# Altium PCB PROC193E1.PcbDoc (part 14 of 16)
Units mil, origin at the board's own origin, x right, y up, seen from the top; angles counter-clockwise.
Board outline 7700 x 2300 mil, 6 copper layers (Top Layer, GND 1, SIG 1, PWR, GND 2, Bottom Layer), stack 60.98 mil thick; 946 components, 667 nets, 9401 pads, 1730 vias.
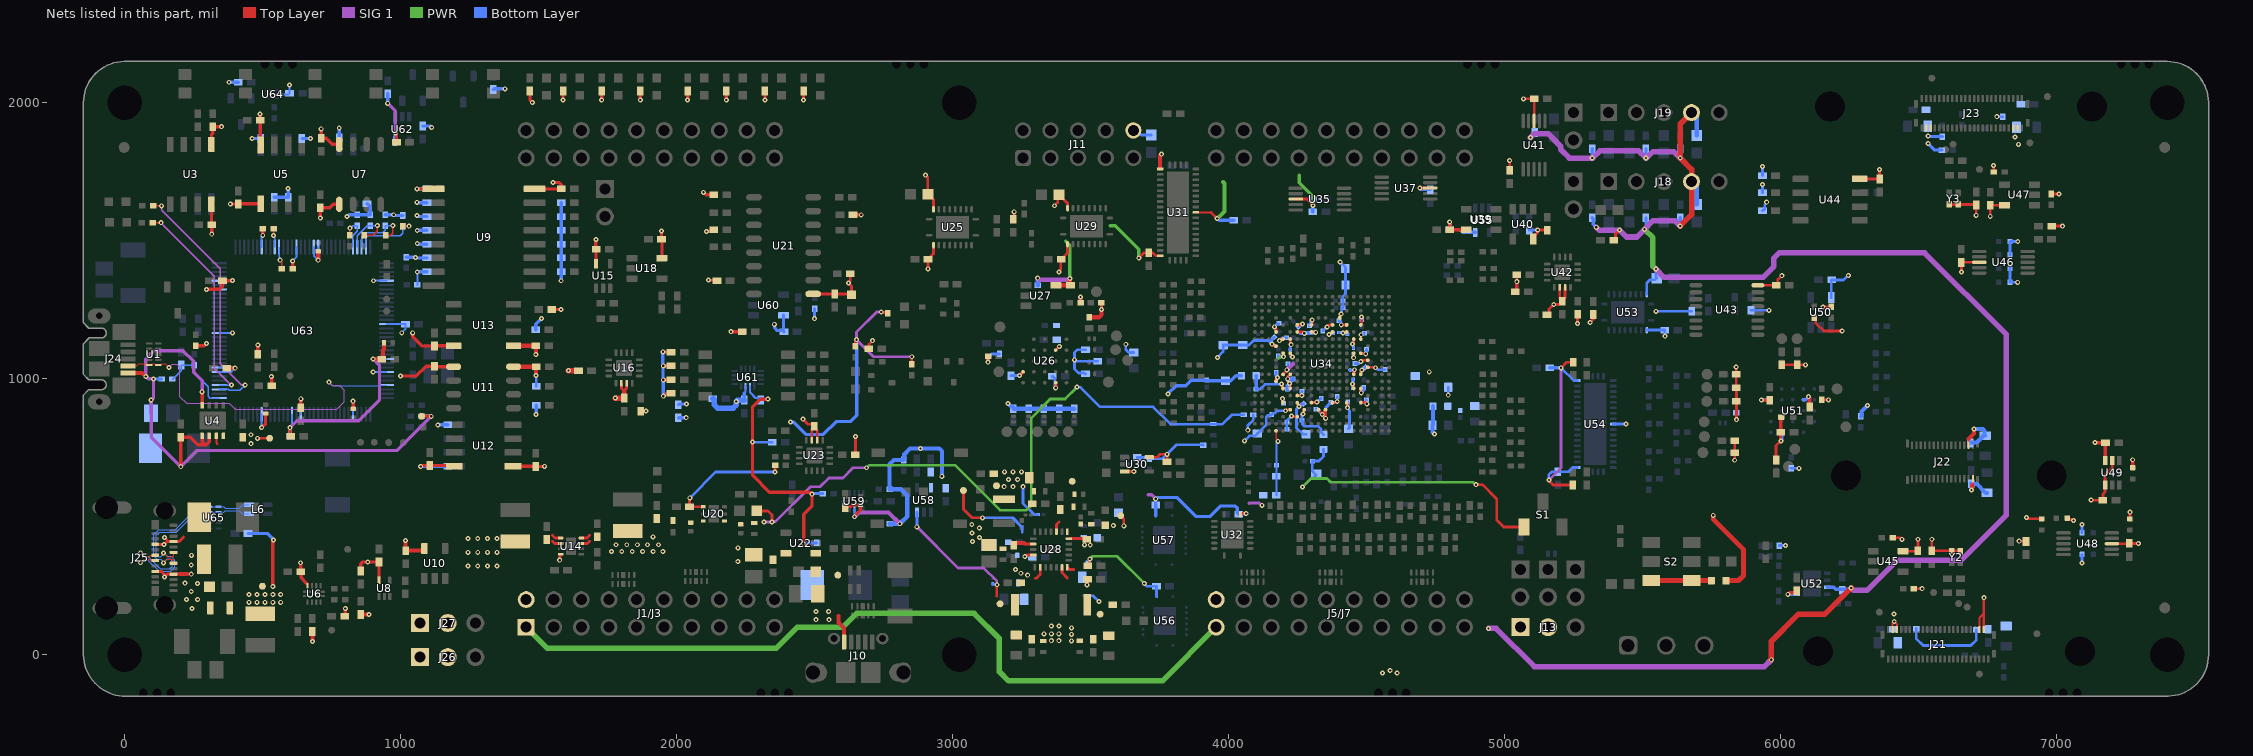
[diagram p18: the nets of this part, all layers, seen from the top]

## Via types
v1: diameter 18, hole 8, Top Layer to Bottom Layer, tented both sides, 1710 vias
v2: diameter 18, hole 8, Top Layer to Bottom Layer, tented top, 12 vias
v3: diameter 23.62, hole 11.81, Top Layer to Bottom Layer, tented both sides, 8 vias

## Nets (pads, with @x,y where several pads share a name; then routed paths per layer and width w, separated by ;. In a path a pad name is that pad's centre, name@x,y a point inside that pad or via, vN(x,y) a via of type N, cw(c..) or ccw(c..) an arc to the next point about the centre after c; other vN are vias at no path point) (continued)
USBTYPEC_DM: J25.A7 J25.B7 L6.1 U65.5 U65.6 | length 833.7
  Top Layer w4.2: v1(57.05,369.66) 70.96,355.74 88.56,355.74 93.92,361.1 J25.B7@109.7,361.1 ; v1(140.74,333.26) 154.14,346.66 173.18,346.66 176.63,343.21 J25.A7@176.63,331.57
  Bottom Layer w4.2: v1(57.05,369.66) 70.44,356.27 83.43,356.27 128.66,311.04 162.68,311.04 171.93,320.3 171.93,339.34 164.1,347.17 154.66,347.17 v1@142.12,334.63 ; v1(140.74,333.26) 140.74,336.01 130.09,346.66 117,346.66 105.46,358.19 105.46,436.7 122.26,453.5 182.76,453.5 260.66,531.4 279.6,531.4 284.84,536.64 U65.5@306.02,536.64 U65.6@338.89,536.64 358.09,536.64 363.34,531.4 414.75,531.4 426.47,543.12 L6.1@449.6,543.12
USBTYPEC_DP: J25.A6 J25.B6 L6.4 U65.4 U65.7 | length 834.3
  Top Layer w4.2: v1(57.05,333.66) 69.93,346.54 88.56,346.54 93.69,341.41 J25.B6@109.7,341.41 ; v1(140.74,369.26) 154.14,355.86 173.18,355.86 176.63,359.3 J25.A6@176.63,370.94
  Bottom Layer w4.2: v1(57.05,333.66) 70.46,347.07 79.62,347.07 124.85,301.84 166.49,301.84 181.13,316.49 181.13,343.15 167.91,356.37 153.62,356.37 142.12,367.88 v1(140.74,369.26) 140.74,366.5 130.09,355.86 120.81,355.86 114.66,362 114.66,432.89 126.07,444.3 186.57,444.3 264.47,522.2 279.6,522.2 284.84,516.95 U65.4@306.02,516.95 U65.7@338.89,516.95 358.09,516.95 363.34,522.2 414.52,522.2 425.09,511.62 L6.4@449.6,511.62
VBUS_MICRO_AB_5V0: C50.1 C51.1 D18.2 J10.1 TP14.1 U22.1 | length 103.2
  Top Layer w12: J10.1@2606.09,46.17 J10.1@2606.19,46.17
  Top Layer w15: 2586.26,141.04 2586.26,116.73 2606.09,96.89 2606.09,72.97 2606.19,72.88 J10.1@2606.19,46.17
  other v1: 2503.91,127.19 2550.94,127.19 2503.91,156.78 2550.3,156.78
VBUS_TYPEC_5V0: C4.1 C5.1 D2.2 J25.A4 J25.A9 J25.B4 J25.B9 L1.1 | length 264.9
  Top Layer w11: J25.B9@109.7,400.47 110.11,400.06 v1(142.29,400.06) 152.53,410.31 196.77,410.31 212.61,426.15 ; v1(143.88,424.98) 155.05,413.81
  Top Layer w11.5: J25.B4@109.7,302.04 132.38,302.04 144,290.42 v1(144,282.09) 154.11,292.2 J25.A9@176.63,292.2 ; J25.A9@176.68,292.25 199.48,292.25
  Top Layer w15: 199.48,292.25 227.68,292.25
  other v1: 243.58,167.7 223.39,199.95 264.16,200.22 240.71,229.19 218.04,259.4 263.8,258.72 240.71,292.2 240.71,325.66 241.5,360.53
VBUS_XDS_5V0: C2.1 C270.1 D19.2 J24.1 R390.2 R415.2 TP12.1 U4.1 U4.2 U4.8 | length 2324.1
  Top Layer w12: v1(202.72,681.67) 202.83,681.78 C2.1@202.83,788.65 237.34,788.65 264.64,761.34 295.51,761.34 ; v1(280.11,952.74) 280.11,903.63 U4.8@280.3,903.44 ; U4.1@280.3,793.2 280.3,772.1 291.07,761.34 295.51,761.34 ; U4.2@305.89,793.2 305.89,771.73 295.51,761.34 ; TP12.1@1075.19,864.22 v1(1110.3,864.22)
  Top Layer w15: J24.1@11.81,1021.01 62.95,1021.01 v1(76.14,1007.82)
  SIG 1 w12: v1(280.11,952.74) 280.11,993.51 249.65,1023.97 249.65,1063.11 210.76,1102 106.61,1102 76.14,1071.53 v1(76.14,1007.82) 77.76,1007.82 85.16,1000.42 103.06,1000.42 v1(104.21,999.27) 104.21,997.65 104.21,931.57 v1(95.75,923.11) 95.75,788.65 v1(202.72,681.67) 261.05,740 986.08,740 v1(1110.3,864.22)
  Bottom Layer w12: C270.1@95,874.79 95,922.36 v1(95.75,923.11) ; v1(104.21,999.27) 104.28,999.2 R415.2@133.15,999.2 ; R390.2@1075.19,864.22 v1(1110.3,864.22)
VCORE_1V2: C64.1 C68.1 C71.1 C179.1 C181.2 C182.2 C183.2 C184.2 C185.2 C187.2 C188.2 C189.2 C190.1 C191.1 C194.2 C196.2 C208.2 C209.1 C212.2 C214.1 C216.1 C217.2 C219.1 C220.1 C222.1 C229.2 C232.2 C235.2 C240.2 L4.2 R349.2 TP19.1 U34.D13 U34.F7 U34.F9 U34.F12 U34.F14 U34.G6 U34.G15 U34.H4 U34.J6 U34.J15 U34.K17 U34.M6 U34.M15 U34.P6 U34.P15 U34.R7 U34.V7 U58.3 | length 1794.3
  Top Layer w10: 3159.52,212.29 3159.52,252.99 v1(3160.37,253.84) ; v1(4156.85,1125.25) 4163.63,1118.47 U34.H4@4171.26,1118.47 ; U34.P6@4222.44,964.93 4222.44,978.49 4220.12,980.8 v1(4220.12,982.97) v1(4213.64,999.83) 4213.64,1007.31 U34.M6@4222.44,1016.11 ; U34.J6@4222.44,1092.88 4223.66,1091.66 4223.66,1086.4 v1(4230.92,1079.13) ; U34.G6@4222.44,1144.06 4222.44,1127.27 v1(4226.03,1123.68) ; v1(4226.67,865.67) 4229.77,862.57 U34.V7@4248.03,862.57 ; U34.R7@4248.03,939.34 v1@4264.31,939.34 ; U34.F7@4248.03,1169.65 4268.92,1169.65 v1(4273.62,1164.95) ; U34.F9@4299.21,1169.65 4299.76,1169.11 4314.34,1169.11 v1(4314.89,1168.56) ; v1(4362.66,1160.97) 4364.19,1162.5 4367.81,1162.5 4374.96,1169.65 U34.F12@4375.98,1169.65 ; U34.D13@4401.57,1220.83 4402.29,1221.56 4402.29,1227.29 4407.15,1232.15 v1(4407.15,1234.31) ; v1(4413.59,1165.65) 4417.59,1169.65 U34.F14@4427.16,1169.65 ; v1(4448.4,1126.08) 4452.75,1130.43 U34.G15@4452.75,1144.06 ; v1(4448.71,980.87) 4452.75,976.83 U34.P15@4452.75,964.93 ; v1(4452.58,1076.43) 4452.75,1076.59 U34.J15@4452.75,1092.88 ; v1(4478.28,1063.05) 4482.52,1067.29 U34.K17@4503.93,1067.29
  Top Layer w12: U34.M15@4452.75,1016.11 4452.75,1029.57 v1(4455.96,1032.77)
  SIG 1 w10: v1(2869.72,463.8) 3019.15,314.38 3111.95,314.38 3159.46,266.87 3159.46,254.75 v1(3160.37,253.84)
  Bottom Layer w10: v1(2869.72,463.8) 2870.04,464.12 U58.3@2870.04,516.32 ; R349.2@3144.53,257.22 3144.53,255.54 3144.7,255.37 3158.84,255.37 v1(3160.37,253.84) ; v1(3626.9,1125.13) 3626.9,1105.14 3637.19,1094.85 C240.2@3655.94,1094.85 ; v1(3958.96,1077.54) 3979.67,1098.25 3979.67,1121.88 C235.2@3979.56,1121.99 3979.84,1122.27 C232.2@4050.77,1122.27 4073.36,1122.27 4090.3,1139.22 C229.2@4106.03,1139.22 4142.88,1139.22 v1@4155.46,1126.63 ; v1(4156.85,1125.25) v1@4155.46,1126.63 ; C222.1@4164,1150.7 4155.46,1142.16 v1@4155.46,1126.63 ; C219.1@4210.38,816.74 C220.1@4210.38,842.29 4210.38,849.38 v1(4226.67,865.67) ; 4213.35,976.19 v1(4220.12,982.97) 4233.88,996.73 C216.1@4233.88,999.6 C216.1@4233.77,999.71 ; v1(4213.64,999.83) v1@4213.75,999.71 ; v1(4226.03,1123.68) 4226.03,1121.51 4222.26,1117.74 C217.2@4222.26,1105.54 4222.26,1082.41 4225.53,1079.13 v1(4230.92,1079.13) ; v1(4264.48,939.17) 4264.68,939.37 4264.68,954.2 C209.1@4264.88,954.4 ; v1(4273.62,1164.95) v1@4274.99,1166.33 ; v1(4362.66,1160.97) 4364.82,1160.97 4368.39,1164.54 4376.76,1164.54 C196.2@4377.67,1165.44 ; C194.2@4398.05,1167.57 4411.67,1167.57 v1(4413.59,1165.65) 4425.12,1165.65 C187.2@4429.67,1161.1 ; v1(4403.62,1423.67) 4422.27,1405.02 C189.2@4422.27,1399.48 ; v1(4407.15,1234.31) 4407.15,1236.48 4409.51,1238.84 4409.51,1253.37 4412.78,1256.63 C190.1@4413.56,1256.63 4413.56,1281.74 C191.1@4413.11,1282.19 4413.11,1298.35 4423.24,1308.48 C188.2@4423.24,1339.92 C189.2@4423.24,1400.28 ; C185.2@4439.34,1031.99 4455.17,1031.99 v1(4455.96,1032.77) ; v1(4448.4,1126.08) 4448.4,1123.91 4450.67,1121.64 4450.67,1112.58 C181.2@4451.57,1111.67 ; C184.2@4449.3,965.79 4449,966.08 4449,980.58 v1(4448.71,980.87) 4450.11,982.28 4450.11,997.54 C182.2@4451.02,998.45 ; C183.2@4450.56,1090.76 4451.47,1089.85 4451.47,1077.54 v1(4452.58,1076.43) ; C179.1@4456.87,1055.34 4470.58,1055.34 v1(4478.28,1063.05)
  Bottom Layer w15: C214.1@4213.35,961.7 4213.35,976.19 ; v1(4213.64,999.83) 4213.64,996.63 4220.12,990.14 v1(4220.12,982.97) ; v1@4213.75,999.71 C216.1@4233.77,999.71 ; C212.2@4260.51,1166.13 4272.44,1166.13 v1(4273.62,1164.95) ; v1@4274.99,1166.33 C208.2@4300.57,1166.33 4301.48,1167.23 4313.56,1167.23 v1(4314.89,1168.56)
  other v1: 3357,51 3384,51 3330,76 3357,76 3384,76 3357,104 3385,104
VDD_1P8: C73.1 C75.1 C76.1 TP25.1 U28.3 | length 38.4
  Top Layer w10: U28.3@3375.64,446.5 3375.64,471.37 3385.19,480.93
VDD_XDS3V3: C3.2 C6.2 C7.2 C9.1 C10.2 C13.1 C14.1 C17.2 C18.1 C19.1 C21.1 C28.1 C29.2 C30.2 C259.1 C261.1 R5.2 R7.2 R9.2 R12.2 R379.2 R382.2 R383.1 R384.1 R385.1 R386.1 R387.1 R388.1 R392.2 R393.2 R394.2 R396.2 R397.1 R398.2 R399.2 R404.2 R406.2 TP2.1 U3.8 U4.3 U4.4 U5.1 U7.1 U9.1 U11.1 U12.8 U13.8 U63.7 U63.8 U63.16 U63.26 U63.28 U63.39 U63.47 U63.51 U63.52 U63.69 U63.79 U63.90 U63.101 U63.113 U63.122 | length 3002.7
  Top Layer w7: U4.3@331.48,793.2 331.48,767.72 335.59,763.62
  Top Layer w8: v1(480.73,784.53) TP2.1@524.75,784.53
  Top Layer w12: R5.2@257.13,1120.19 287.58,1120.19 294.88,1127.49 v1(296.51,1127.49) ; v1(296.51,1323.98) 342.35,1323.98 354.12,1335.75 C6.2@354.12,1355.66 v1(390,1355.66) ; U3.8@314.01,1632.55 314.01,1559.47 C3.2@314.83,1558.65 314.83,1524.17 v1(315,1524) ; C7.2@368.94,1038.47 v1(400,1038.47) ; v1(382.15,1633.29) C9.1@411.06,1633.29 412.28,1634.52 U5.1@491.82,1634.52 ; R7.2@481.97,1088.85 v1(481.97,1122.33) ; v1(496.08,823.57) 510,837.49 C14.1@510,874.4 ; v1(499.83,1519.85) 500,1520.01 R9.2@500,1543.19 ; v1(530.73,1008.1) 530.73,1006.48 532.27,1004.94 C13.1@532.27,974.76 ; R12.2@608.84,1399.46 v1@608.84,1426.48 ; C17.2@637.63,894.84 v1(637.63,927.56) ; v1(708.51,1582.82) C19.1@708.51,1619.96 743.12,1619.96 755.48,1632.31 U7.1@777.09,1632.31 ; v1(826.42,918.87) 827.49,917.8 C21.1@827.49,891.07 ; v1(999.09,1010.35) 1056.59,1010.35 1091.78,1045.54 C29.2@1122.11,1045.54 1124.06,1043.59 U11.1@1191.5,1043.59 ; v1(1043.03,1166.68) 1043.03,1152.11 1076.27,1118.86 C30.2@1122.11,1118.86 1122.97,1119.73 U13.8@1191.73,1119.73 ; v1(1058.6,1688.24) 1058.9,1687.95 U9.1@1118.64,1687.95 ; v1(1072,682.5) 1073.62,682.5 1076.9,685.78 1190.95,685.78 U12.8@1193.7,683.03
  Top Layer w15: v1(700.81,1429.87) C18.1@700.81,1457.63
  Bottom Layer w7: v1(296.51,1323.98) U63.26@342.35,1323.98 ; U63.7@342.35,1024.76 386.3,1024.76 v1(400,1038.47) 397.96,1040.51 U63.8@342.35,1040.51 ; U63.16@342.35,1166.5 v1@389.81,1166.5 ; U63.28@342.35,1355.47 v1@389.81,1355.47 ; v1@495.89,823.76 U63.122@495.89,871.22 ; U63.39@495.89,1477.52 495.89,1515.91 v1(499.83,1519.85) ; v1(608.19,1427.13) 621.88,1440.82 U63.47@621.88,1477.52 ; U63.113@637.63,871.22 v1@637.63,918.68 ; U63.51@684.87,1477.52 684.87,1445.81 700.62,1430.06 U63.52@700.62,1477.52 ; U63.101@826.6,871.22 v1@826.6,918.68 ; v1@900,1024.76 U63.90@948.65,1024.76 ; v1@901.19,1355.47 U63.69@948.65,1355.47 ; U63.79@948.65,1197.99 C261.1@1016.88,1197.99 1016.88,1180.12 v1(1003.44,1166.68) ; v1(1059.56,1387.43) 1060.19,1386.81 R392.2@1060.19,1340.39
  Bottom Layer w8: v1@389.81,1166.5 v1(390,1166.68) ; v1@389.81,1355.47 v1(390,1355.66) ; v1@495.89,823.76 v1(496.08,823.57) ; v1@637.63,918.68 v1(637.63,927.56) ; v1(826.42,918.87) v1@826.6,918.68 ; v1(899.81,1024.58) v1@900,1024.76 ; v1(901,1355.28) v1@901.19,1355.47
  Bottom Layer w12: R406.2@541.82,1658.14 R404.2@591.82,1658.14 591.75,1658.2 591.75,1688.94 v1(591.69,1689.01) ; v1(804.99,1587.77) 806.62,1587.77 813.22,1594.37 R398.2@889.13,1594.37 889.13,1623.21 R397.1@877.57,1634.77 ; R396.2@943.35,1594.37 v1(974.31,1594.37) 977,1591.68 R394.2@1007.56,1591.68 ; R393.2@1020,1440.93 1051.47,1440.93 v1(1052.8,1439.6) 1054.46,1437.95 R384.1@1095.02,1437.95 ; v1(1058.6,1591.68) 1062.34,1587.95 R387.1@1095.02,1587.95 ; v1(1058.6,1639.54) 1060.19,1637.95 R388.1@1095.02,1637.95 ; v1(1058.6,1688.24) 1058.9,1687.95 C259.1@1095.02,1687.95 ; v1(1059.56,1387.43) 1060.08,1387.95 R383.1@1095.02,1387.95 ; v1(1059.56,1490.13) 1061.75,1487.95 R385.1@1095.02,1487.95 ; v1(1059.56,1536.84) 1060.67,1537.95 R386.1@1095.02,1537.95 ; v1@1072.52,683.03 R379.2@1170.08,683.03 ; v1@1134.28,833.03 R382.2@1170.08,833.03
  other v1: 457.48,764.8 457.27,797.27 1134.25,833.06
VDDA18_AM261_OSC_PLL: C210.1 FB3.2 U34.U8 | length 155.3
  Top Layer w10: v1(4269.04,872.85) U34.U8@4273.62,888.16
  Bottom Layer w10: v1(4269.04,872.85) 4264.31,868.13 C210.1@4264.31,849.86 4267.33,846.85 4267.33,834.34 4273.19,828.48 4323.26,828.48 4335.36,816.38 4335.36,805.41 4343.16,797.62 FB3.2@4343.27,797.62
VDDA_AM261_1V8_LDO: C197.1 C202.1 C204.1 C205.1 C218.1 FB3.1 R320.2 S1.1 U34.T5 U34.U10 U34.U11 | length 1409.1
  Top Layer w10: v1(4195,928) 4196.12,926.88 4196.12,914.47 U34.T5@4196.85,913.75 ; U34.U10@4324.8,888.16 4324.8,887.13 v1@4337,874.93 ; v1(4351.18,856.94) v1@4350.39,857.78 ; v1(4895.19,616.35) 4919.51,616.35 4970.75,565.12 4970.75,488.24 4996.06,462.93 S1.1@5069.76,462.93 ; v1@4350.39,857.78 U34.U11@4350.39,888.16 v1(4338.53,870.34) v1@4350.39,857.78
  PWR w10: v1(4266.94,607.69) 4298.25,639 4355.69,639 4369.34,625.35 4885.33,625.35 4894.33,616.35 v1(4895.19,616.35)
  Bottom Layer w10: v1(4068.8,813.88) 4068.8,830.35 4089.02,850.57 R320.2@4089.02,869.83 ; v1(4195,928) 4196.53,926.47 4196.53,913.39 C218.1@4196.85,913.07 ; v1(4266.94,607.69) 4297.71,638.46 4303.29,638.46 C202.1@4316.99,652.16 ; C202.1@4316.15,652.16 4302.45,665.86 C205.1@4302.45,701.73 4325.9,701.73 4343.27,719.1 FB3.1@4343.27,744.47 ; C204.1@4316.46,890.38 4317.25,890.38 4322.92,884.71 4323.9,884.71 4338.27,870.34 v1(4338.53,870.34) ; v1(4351.18,856.94) 4351.18,895.05 4369.18,913.04 C197.1@4369.18,913.83
VDDA_AM261_3V3: C161.2 C193.1 C201.1 FB2.2 U34.T9 U34.T12 | length 182.3
  Top Layer w10: U34.T9@4299.21,913.75 4316.56,913.75 v1(4318.94,916.13) ; U34.T12@4375.98,913.75 4388.45,913.75 v1(4392.89,918.18)
  Bottom Layer w10: v1(4318.94,916.13) 4331.8,928.99 C201.1@4335.28,928.99 ; C193.1@4392.64,934.88 4392.64,918.43 v1(4392.89,918.18)
  Bottom Layer w15: FB2.2@4740.2,900.65 4740.2,833.29 C161.2@4738.43,831.52 4738.43,805.98 v1(4744.79,799.61)
VDDA_AM261_3V3_USB: C230.1 FB4.2 U34.P5 | length 165.7
  Top Layer w12: v1(4190.91,980.87) U34.P5@4196.85,964.93
  Bottom Layer w10: C230.1@4098.94,962.34 4113.43,962.34 4131.11,980.02 v1@4190.06,980.02
  Bottom Layer w12: C230.1@4098.94,962.34 4099.36,962.76 FB4.2@4099.36,1011.24 ; v1@4190.06,980.02 v1(4190.91,980.87)
VDDC_XDS_1V0: C16.2 C23.2 C25.1 C265.2 U63.87 U63.115 | length 782.3
  Top Layer w12: v1(598.48,823) 598.48,794.73 C16.2@601.36,791.85
  Top Layer w15: v1(899.81,1071.82) 899.97,1071.67 931.29,1071.67 C23.2@931.38,1071.57 935,1075.2 935,1104 939.25,1108.25 C25.1@939.25,1130
  SIG 1 w12: v1(598.48,823) 623.9,848.42 848.11,848.42 922.69,923 922.69,1048.95 v1(899.81,1071.82)
  Bottom Layer w7: v1(598.48,823) 606.13,830.65 U63.115@606.13,871.22 ; v1@900,1072.01 U63.87@948.65,1072.01
  Bottom Layer w8: v1(899.81,1071.82) v1@900,1072.01
  Bottom Layer w12: v1(598.48,823) 598.48,794.73 C265.2@601.36,791.85
VDDS_AM261_LDO_1V8: C169.1 C173.1 C175.1 C192.1 C203.1 C221.1 C225.1 C226.1 C228.2 U34.E9 U34.E14 U34.F4 U34.G16 U34.L17 U34.N4 U34.T16 U34.U6 | length 523.7
  Top Layer w5.3: U34.G16@4478.34,1144.06 v1(4479.82,1159.59)
  Top Layer w10: v1(4165.38,1188.34) 4171.26,1182.46 U34.F4@4171.26,1169.65 ; U34.N4@4171.26,990.52 4171.26,998.99 v1(4176.62,1004.36) ; v1(4205.94,884.23) 4209.87,888.16 U34.U6@4222.44,888.16 ; U34.E9@4299.21,1195.24 4302.23,1198.26 4302.23,1210.39 v1(4302.23,1212.56) ; v1(4407.45,1195.74) 4407.94,1195.24 U34.E14@4427.16,1195.24 ; U34.T16@4478.34,913.75 4495.85,913.75 v1(4500.08,909.51) ; U34.L17@4503.93,1041.7 4530.07,1041.7 v1(4531.79,1039.99)
  Bottom Layer w10: v1(4056.62,775.42) 4074.57,793.37 4094.41,793.37 C228.2@4103.27,802.23 4105.04,802.23 4135.28,832.47 4135.28,861.65 4141.14,867.51 4152.99,867.51 4156.26,870.77 4156.26,871.71 4159.53,874.97 4165.77,874.97 4174.26,883.47 4177.62,883.47 4178.47,884.32 v1@4205.85,884.32 ; v1(4165.38,1188.34) 4176.54,1199.49 C221.1@4181.23,1199.49 ; C225.1@4171.17,1023.47 4171.17,1009.81 v1(4176.62,1004.36) ; C203.1@4291.66,1192.22 4292.45,1192.22 4295.72,1195.49 4295.72,1206.04 v1(4302.23,1212.56) ; C192.1@4399.46,1209.55 4407.45,1201.56 v1(4407.45,1195.74) ; v1(4479.82,1159.59) 4484.77,1159.59 C173.1@4490.94,1165.76 ; C175.1@4498.34,924.43 4498.34,911.25 v1(4500.08,909.51) ; v1@4532.45,1040.64 4539.89,1033.19 C169.1@4566.16,1033.19
VPP_AM261_1V7: C46.2 C48.1 R59.2 R321.2 R323.2 U20.1 | length 2418.2
  Top Layer w10: R59.2@2289.61,521.35 2330.78,521.35 2345.05,507.08 v1(2345.05,481.55)
  SIG 1 w10: v1(2316.06,481.55) v1(2345.05,481.55) 2346.05,482.55 2357.99,482.55 2484.16,608.72 2519.08,608.72 2550.91,640.55 2601.82,640.55 2638.96,677.7 v1(2687.67,677.7)
  PWR w10: v1(2687.67,677.7) 2688.09,677.7 2697.53,687.14 3007.66,687.14 3170.81,523.99 3266.51,523.99 3284.54,542.02 3284.54,857.93 3353.01,926.4 3407.14,926.4 3450.01,969.27 v1(3450.01,970.53)
  Bottom Layer w10: v1(3450.01,970.53) 3451.36,969.18 3462.61,969.18 3533.44,898.35 3725.86,898.35 3788.62,835.59 R323.2@3943.1,835.59 3976.69,835.59 4010.93,869.83 R321.2@4053.85,869.83
VPP_LDO_EN: R50.2 R64.2 U20.4 | length 454.6
  Top Layer w10: v1(2047.23,568.72) 2045.95,567.45 R50.2@2045.95,536.03 U20.4@2095.72,536.03 ; v1(2356,662) 2356.07,662.07 2356.07,686.04 R64.2@2356.14,686.11
  Bottom Layer w10: v1(2047.23,568.72) 2140.51,662 v1(2356,662)
VREG: C249.1 C250.1 TP15.1 U28.11 | length 358.3
  Top Layer w10: TP15.1@3038.48,595.4 3038.48,527.49 3069.52,496.45 v1(3107.08,496.45) ; v1@3261.13,355.89 3263.12,355.89 3269.08,361.86 U28.11@3290.99,361.86
  Bottom Layer w10: v1(3107.08,496.45) 3217.16,496.45 3251.4,462.22 3251.4,444.14
  other v1: 3260.95,355.89
VSYS_1V8: C59.2 C72.2 C78.1 C83.1 C84.2 C115.1 C117.1 C118.1 C120.1 C127.1 C133.1 C135.1 C136.1 C137.1 C146.2 C162.2 C176.1 C223.1 C241.2 C246.1 C247.1 C248.1 C253.1 FB1.1 J22.2 J22.3 R89.1 R99.2 R102.2 R193.1 R194.1 R196.1 R197.1 R198.1 R199.2 R203.1 R204.1 R205.2 R206.2 R207.2 R250.2 R255.1 R335.1 R336.1 R337.2 R339.1 R340.2 R341.1 R342.1 R345.1 R347.1 R348.2 TP31.1 U25.2 U26.B4 U26.D1 U26.E4 U28.1 U29.2 U30.3 U34.J5 U34.P16 U49.1 U49.5 U51.B4 U51.D1 U51.E4 U53.2 | length 3103.8
  Top Layer w7: J22.3@6680.37,759.66 6680.37,782.25 ; 6693.17,612.9 6696.12,615.85 J22.2@6696.12,638.4
  Top Layer w10: v1(2910.13,1398.63) C59.2@2910.13,1433.48 2930.07,1453.41 U25.2@2930.07,1484.11 ; v1(3127.61,1060.13) R89.1@3127.61,1081.34 ; v1(3241.2,1011.73) v1@3241.2,1011.91 ; U26.E4@3372.63,985.86 U26.E4@3372.71,985.86 ; U26.B4@3372.63,1103.97 v1@3385.95,1117.29 ; v1(3384.77,1387.08) 3384.77,1389.25 3390.82,1395.3 3390.82,1431.36 C72.2@3393.37,1433.91 3415.76,1456.29 U29.2@3415.76,1488.24 ; v1(3538.64,1250.73) R102.2@3538.64,1275.27 ; TP31.1@3607.79,504.1 3619.55,492.35 v1(3619.55,467.35) ; U30.3@3623.07,664.21 3655.76,664.21 v1(3655.94,664.03) ; U34.J5@4196.85,1092.88 4197.42,1092.3 4197.42,1080.58 v1(4198,1080) ; v1(5832.8,704.92) R193.1@5832.8,731.78 R194.1@5832.8,775.07 ; v1(5838.48,1042.63) 5838.29,1042.44 R196.1@5838.29,1015.72 5838.29,967.19 R197.1@5838.48,967 5839.07,966.41 R198.1@5839.07,917.95 5839.07,851.9 v1(5839.25,851.72) ; v1(5929.42,922.71) v1@5930.4,921.72 ; R203.1@5982.95,706.02 5982.95,757.79 v1(6000.23,775.07) ; C117.1@6000.23,805.84 C117.1@6001.56,807.17 ; R204.1@6003.63,1050.69 R205.2@6058.96,1050.69 v1(6089.46,1050.69) ; R206.2@6121.79,1220.95 6126.39,1216.35 6126.39,1202.68 6156.2,1172.87 v1(6222.32,1172.87) ; R207.2@6148.3,924.06 6172.55,924.06 v1(6172.8,923.81) ; v1(7124.57,560.92) 7125.72,559.77 C127.1@7167.02,559.77 7167.02,581.65 7175.09,589.72 U49.1@7175.09,615.29 7175.09,651.51 7200.68,677.1 U49.5@7200.68,703.87
  Top Layer w12: v1@3241.2,1011.91 U26.D1@3254.52,1025.23 ; v1(3372.67,967.47) 3372.67,985.82 U26.E4@3372.71,985.86 ; U34.P16@4478.34,964.93 4478.34,950.65 v1(4479.84,949.15) ; v1@5930.4,921.72 C115.1@5959.69,921.72 ; v1(6000.23,775.07) 5998.91,776.39 5998.91,804.52 C117.1@6000.23,805.84 6000.23,859.97 C118.1@6001.56,861.29
  Top Layer w15: v1(3462.71,1296.26) 3462.83,1296.26 R99.2@3462.83,1274.81 ; R340.2@3494.85,1223.08 3530.27,1223.08 3538.64,1231.45 v1(3538.64,1250.73) ; v1(6100.62,935.27) 6100.62,934.46 6104.06,931.02 C120.1@6104.06,898.17 ; 6680.37,782.25 6699.91,801.79 v1@6699.91,817.51 ; v1(6691.19,597.33) 6691.19,598.14 6693.17,600.12 6693.17,612.9
  Top Layer w18: v1(5755.22,505.29) 5755.22,491.1 5865.21,381.11 5865.21,287.36 5846.79,268.94 FB1.1@5801.3,268.94
  PWR w10: 4179.7,1073.51 4185.12,1078.93 4196.93,1078.93 v1(4198,1080)
  Bottom Layer w10: v1(3127.61,1060.13) 3127.61,1076.72 3141.01,1090.12 R348.2@3169.16,1090.12 ; C253.1@3210.86,1010.92 C253.1@3211.67,1011.73 ; C246.1@3360.16,1008.52 3362.72,1008.52 3369.53,1001.71 3369.53,972.78 3372.67,969.64 v1(3372.67,967.47) ; R336.1@3480.51,1017.79 3476.92,1021.38 3455.62,1021.38 3440.86,1036.14 v1(3440.86,1068.67) ; R337.2@3480.51,1105.45 3451.6,1105.45 3440.86,1094.71 v1(3440.86,1068.67) ; R335.1@3525.15,1063.53 3446,1063.53 v1(3440.86,1068.67) ; C223.1@4179.24,1082.76 4180.62,1081.38 4196.62,1081.38 v1(4198,1080) ; v1(4479.84,949.15) 4489.53,958.84 C176.1@4489.53,968.92 ; v1(4795.12,940.61) 4795.23,940.72 4795.23,945.25 C162.2@4795.23,969.1 ; U53.2@5514.38,1176.44 C146.2@5579.86,1176.44 5579.86,1154.52 v1(5580.01,1154.36) ; v1@5839.41,851.89 R199.2@5839.41,877.17 ; R255.1@6037.35,675.66 6065.38,675.66 v1(6065.44,675.6)
  Bottom Layer w12: C253.1@3211.67,1011.73 v1(3241.2,1011.73) ; v1(5929.42,922.71) 5930.43,923.71 U51.E4@5964.26,923.71 ; v1(6000.23,775.07) 6003.63,778.46 U51.D1@6003.63,805.6 ; U51.B4@6082.37,923.71 6082.63,923.98 6090.17,923.98 6100.62,934.44 v1(6100.62,935.27)
  Bottom Layer w15: v1(3200.26,910.56) 3211.03,899.79 3215.43,899.79 3219.74,895.47 R347.1@3219.74,891.54 R345.1@3274.55,891.54 R342.1@3330.3,891.54 R341.1@3384.85,891.54 R339.1@3440.45,891.54 ; R250.2@6290.18,863.61 6292.53,865.95 6292.53,881.53 v1(6314,903) ; C137.1@6686.31,767.34 6687.58,768.61 6710.02,768.61 6735.34,793.93 C135.1@6740.26,793.93 6738.15,796.05 6738.15,811.8 6732.29,817.65 v1(6700.06,817.65) ; C136.1@6689.31,620.21 6690.62,618.9 C136.1@6690.62,618.8 ; C136.1@6690.49,618.8 C136.1@6690.62,618.8 ; v1(6691.19,597.33) 6690.62,597.9 C136.1@6690.62,618.8 ; C133.1@6747.24,586.74 6742.32,586.74 6710.26,618.8 C136.1@6690.62,618.8
  other v1: 3581.66,468.03 3385.95,1117.47
VSYS_2V5: C77.1 C82.1 C85.1 C130.1 C131.1 C140.1 C141.1 J21.4 J21.6 J23.4 J23.6 L5.2 R107.2 R338.2 TP27.1 | length 109
  Top Layer w8: J21.4@6404.81,91.39 6404.81,114.35 v1(6411.01,120.55) 6420.56,111.01 J21.6@6420.56,91.39
  Bottom Layer w10: R338.2@3493.97,214.09 3508.56,214.09 v1(3529.49,193.16)
  other v1: 4557.1,-65.85 4610.24,-66.03 4584.64,-56.5 3429.55,50.79 3429.55,74.19 3430.39,97.72 6409.99,147.31 6861.42,1849.7 6849.07,1875.92
VSYS_3V3: C8.2 C26.2 C32.2 C33.2 C34.1 C52.1 C53.1 C54.2 C55.2 C56.1 C58.1 C66.1 C67.1 C69.1 C70.1 C74.1 C79.1 C81.1 C86.2 C87.1 C103.2 C107.2 C108.2 C109.1 C116.2 C119.2 C121.2 C122.1 C123.1 C124.2 C125.1 C126.1 C128.2 C129.2 C132.1 C134.1 C138.1 C139.1 C143.1 C154.1 C156.1 C158.2 C159.1 C160.2 C163.2 C165.2 C172.1 C174.1 C177.1 C180.2 C186.1 C198.2 C200.1 C206.2 C207.1 C211.1 C213.1 C215.1 C231.2 C233.2 C234.2 C236.1 C237.1 C238.2 C239.1 C243.2 C244.1 C245.1 C255.1 C256.2 C257.2 C266.2 FB2.1 FB4.1 J11.10 J13.1 J21.44 J21.46 J23.44 J23.46 L3.2 R26.2 R30.1 R38.2 R41.2 R42.2 R46.1 R47.1 R48.1 R49.1 R52.2 R54.1 R56.1 R57.2 R58.2 R61.2 R62.2 R67.2 R73.2 R76.1 R77.1 R81.2 R87.2 R91.1 R175.1 R183.2 R184.1 R185.2 R186.1 R187.1 R188.1 R191.1 R208.2 R209.2 R210.2 R215.2 R217.1 R219.1 R220.2 R221.2 R222.2 R223.2 R224.2 R225.2 R226.2 R227.2 R228.2 R229.2 R230.2 R232.2 R234.2 R237.2 R238.1 R240.2 R257.2 R258.1 R259.1 R260.1 R266.1 R275.1 R301.1 R316.1 R322.2 R333.1 R334.2 R343.2 R344.2 R350.2 R353.1 R355.1 R356.1 R357.1 R360.1 R361.2 R364.1 R367.1 R375.1 R376.1 R377.1 R378.2 R389.2 R395.2 R410.2 TP16.1 U3.1 U11.8 U12.1 U13.1 U21.1 U23.14 U23.15 U25.19 U27.5 U28.19 U28.24 U29.19 U30.5 U31.1 U31.17 U31.30 U32.16 U34.E7 U34.E12 U34.E16 U34.G5 U34.J16 U34.M5 U34.M16 U34.T7 U34.T14 U35.8 U37.8 U39.5 U40.5 U41.8 U42.14 U42.15 U43.16 U44.8 U45.5 U46.8 U47.5 U48.8 U49.6 U50.5 U52.5 U54.1 U54.17 U54.30 U55.5 U56.16 U57.16 U58.5 U59.3 U60.5 U61.2 U62.5 U64.5 Y2.1 Y2.4 Y3.1 Y3.4 | length 12694.6
  Top Layer w6: C103.2@4800.52,1540.34 C103.2@4800.63,1540.23
  Top Layer w7: U31.30@3881.04,1602.98 3936.22,1602.98
  Top Layer w8: J21.44@6719.77,91.39 6719.77,134.11 6735.52,149.86 ; J21.46@6735.52,91.39 6735.52,149.86 ; v1(6736.23,206.96) 6735.52,206.24 6735.52,149.86
  Top Layer w10: R30.1@1547.28,1251.09 v1(1580.01,1251.09) ; v1(2114.42,1357.47) 2115.26,1356.63 2144.88,1356.63 R57.2@2145.72,1355.79 ; v1(2457.71,853.56) 2476.34,834.93 2490.48,834.93 C52.1@2497.29,828.09 C52.1@2497.29,824.15 ; U23.15@2488.85,777.27 2488.85,815.71 C52.1@2497.29,824.15 ; U23.14@2508.54,777.27 2508.54,812.9 C52.1@2497.29,824.15 ; C54.2@2610.25,533.64 2613.81,537.2 2631.2,537.2 2637,543 C56.1@2665.63,543 ; v1@2622.61,1347.47 2628.07,1352.93 R73.2@2628.07,1381.36 ; v1@2643,500 2643,501 2665.63,523.63 C56.1@2665.63,542.74 ; R77.1@2647.45,724.97 2647.45,766.04 2647.7,766.28 v1(2647.7,790.46) ; R81.2@2695.66,1108.27 2695.66,1124.43 v1(2709.37,1138.15) ; v1(2901.02,1737.65) 2908.84,1729.83 2908.84,1670.14 C58.1@2910.3,1668.67 2930.07,1648.9 U25.19@2930.07,1614.03 ; R91.1@3222.24,1578.29 3222.4,1578.45 3222.4,1604.76 v1(3222.55,1604.92) ; v1(3368,1627) 3380.03,1639.03 3380.03,1662.04 C70.1@3384.86,1666.87 3385.85,1666.87 3399.55,1653.17 3399.55,1652.19 3415.76,1635.98 U29.19@3415.76,1618.16 ; U28.19@3415.01,317.07 3423.27,308.81 3438.58,308.81 ; U28.24@3420.91,420.91 3475.39,420.91 C79.1@3476.56,422.08 ; C81.1@3489.4,321.86 3489.64,321.86 3496.45,328.67 v1(3496.45,347.6) ; v1@3674.06,1437.64 3693.55,1457.13 C86.2@3708.5,1457.13 ; C86.2@3709.69,1457.09 3723.94,1457.09 3735.54,1445.5 U31.17@3751.12,1445.5 ; U30.5@3711.65,715.39 3739.49,715.39 3750.65,726.55 v1(3776.03,726.55) 3776.29,726.29 C87.1@3776.29,700.29 ; 3936.22,1602.98 v1(3958.07,1581.14) ; U32.16@4042.61,512.03 4063.1,512.03 v1(4063.16,512.1) ; v1(4183.68,1138.06) 4189.68,1144.06 U34.G5@4196.85,1144.06 ; U34.M5@4196.85,1016.11 4210.32,1029.59 v1(4210.32,1032.7) ; U35.8@4242.38,1651.01 4282.19,1651.01 v1(4305.32,1627.88) ; U34.T7@4248.03,913.75 4254.68,907.1 v1(4254.68,899.66) ; U34.E7@4248.03,1195.24 4263.4,1195.24 v1(4266.66,1198.5) ; v1(4356.44,1188.2) 4363.49,1195.24 U34.E12@4375.98,1195.24 ; U34.T14@4427.16,913.75 4430.08,910.83 v1(4430.08,895.21) ; U34.M16@4478.34,1016.11 4478.34,1027.83 v1(4481.93,1031.41) ; U34.J16@4478.34,1092.88 4493.98,1092.88 v1(4496.21,1090.65) ; U34.E16@4478.34,1195.24 4478.34,1196.27 4481.87,1199.79 v1@4481.87,1221.18 ; v1(4692.03,1691.44) 4692.4,1691.08 U37.8@4729.47,1691.08 ; R175.1@5017.69,1755.06 v1(5017.69,1791.39) ; v1(5043.6,1351.96) R184.1@5043.6,1376.37 ; v1(5067.57,2014.55) C107.2@5106.65,2014.55 5106.65,1934.93 U41.8@5105.92,1934.2 ; U40.5@5103.22,1505.94 5103.22,1513.82 5117.7,1528.3 5117.7,1538.03 v1(5119.23,1539.57) ; v1@5120.71,1538.08 5122.2,1539.57 5152.3,1539.57 C108.2@5153.78,1538.08 ; R185.2@5152.74,1231.83 5153.78,1231.83 5160.59,1238.64 5160.59,1252.75 v1(5177.38,1269.55) 5196.09,1269.55 C109.1@5208.02,1281.48 ; v1(5159.85,633.29) 5159.85,631.13 5163.85,627.13 5163.85,626.88 5175.52,615.2 R186.1@5246.75,615.2 ; U42.14@5198.68,1331.1 5198.68,1290.83 C109.1@5208.02,1281.48 ; v1(5203.87,1039.77) 5224.31,1060.21 R187.1@5247.81,1060.21 ; C109.1@5208.02,1280.43 C109.1@5208.02,1281.48 ; U42.15@5218.36,1331.1 5218.36,1291.82 C109.1@5208.02,1281.48 ; v1(5263.64,1200.11) R188.1@5263.64,1234.24 ; v1(5309.26,1203.92) 5321.3,1215.96 R191.1@5321.3,1233.1 ; U43.16@5916.65,1339.06 C116.2@5982.45,1339.06 ; C116.2@5983.13,1338.39 C116.2@5982.45,1339.06 ; v1(6003.63,1373.63) 5989.34,1359.34 5989.34,1345.2 5983.2,1339.06 C116.2@5982.45,1339.06 ; v1(6152.64,1260.32) R208.2@6182.93,1260.32 ; U44.8@6285.74,1724.05 6357.94,1724.05 v1(6357.97,1758.31) ; R209.2@6405.63,424 6431.41,424 6436.96,418.45 v1(6439.12,418.45) ; U45.5@6443,375.59 6495.71,375.59 C122.1@6496.77,376.64 v1(6496.77,418.65) ; R210.2@6482.37,239.5 v1(6512.17,239.5) ; v1(6547.26,418.65) C123.1@6547.26,376.64 6618.65,376.64 Y2.1@6619.35,375.95 Y2.4@6650.85,375.95 ; Y3.4@6610.65,1631.56 Y3.1@6642.15,1631.56 6706.08,1631.56 C125.1@6708.05,1629.59 v1(6708.05,1592.26) ; v1(6655.1,1387.02) 6655.1,1420.97 C124.2@6654.37,1421.7 6654.89,1422.22 U46.8@6719.18,1422.22 ; v1(6758.89,1588.61) 6758.52,1588.97 C126.1@6758.52,1628.78 6758.69,1628.95 U47.5@6810.6,1628.95 ; v1(6771,1772.8) 6771.23,1772.57 R215.2@6771.23,1749.22 ; v1(6863.87,411.52) 6887.55,411.52 R217.1@6888.43,410.64 ; v1(6890.54,497.35) 6892.7,497.35 6897.43,492.62 R220.2@6945.06,492.62 ; R221.2@6980.08,1669.53 v1(7007.95,1669.53) ; R219.1@6981.28,1553.28 7019.86,1553.28 v1(7020.13,1553) ; R222.2@7038.06,495 7042.41,490.65 7053.63,490.65 7058.02,486.26 v1(7060.19,486.26) ; U48.8@7199.34,402.52 7261.88,402.52 C129.2@7263.05,403.7 7294.69,403.7 v1(7295.19,403.19)
  Top Layer w12: U3.1@314.01,1849.08 314.01,1883.97 318.73,1888.68 C8.2@318.73,1913.27 349.92,1913.27 v1(350.09,1913.44) ; v1(980.29,1891.03) 980.29,1889.4 984.24,1885.45 C26.2@984.24,1856.71 ; U12.1@1406.3,683.03 1488.71,683.03 C34.1@1489.23,682.5 1520.22,682.5 v1(1520.75,683.03) ; R26.2@1467.87,2042.56 1467.87,2011.33 1476.35,2002.85 v1(1476.35,2001.53) ; v1(1587.87,2010) R38.2@1587.87,2042.56 ; v1(1727.87,2010) R41.2@1727.87,2042.56 ; v1(1867.87,2010) R42.2@1867.87,2042.56 ; v1(1950.36,1097.68) 1950.68,1097.36 1978.76,1097.36 R49.1@1979.24,1096.88 ; v1(1951.13,936.88) 1952.75,936.88 1962.75,946.88 R46.1@1979.24,946.88 ; v1(1951.13,996.31) 1951.41,996.6 1978.95,996.6 R47.1@1979.24,996.88 ; v1(1951.13,1046.99) 1951.19,1046.94 R48.1@1979.24,1046.88 R48.1@1979.24,1046.88 ; v1(2039.29,2010) R52.2@2039.29,2042.56 ; v1(2096.84,1675.74) 2097.86,1675.74 2106.64,1666.96 R56.1@2134.14,1666.96 ; v1(2107.91,1533.45) 2109.06,1534.6 2129.44,1534.6 R54.1@2134.14,1539.3 ; v1(2179.29,2010) R58.2@2179.29,2042.56 ; v1(2196.39,1170.68) R61.2@2236.93,1170.68 ; v1(2319.29,2010) R62.2@2319.29,2042.56 ; v1(2329.67,926.4) 2302.47,926.4 2274.42,898.35 v1(2274.42,770.71) 2274.42,650.32 2335.56,589.17 2480.9,589.17 2488.01,582.06 v1(2490.18,582.06) 2490.18,539.58 2459.59,508.99 v1(2459.58,402.06) ; v1(2459.29,2010) R67.2@2459.29,2042.56 ; U21.1@2494.12,1307.42 C53.1@2572.78,1307.42 C55.2@2632.78,1307.42 ; v1@2622.61,1347.47 v1(2622.08,1346.94) 2632.78,1336.24 C55.2@2632.78,1304.27 ; R76.1@2638.47,1593.98 2668.2,1593.98 v1(2668.26,1594.04) ; v1(4800.44,1568.29) 4800.44,1540.42 C103.2@4800.52,1540.34 ; C103.2@4800.63,1540.23 U39.5@4860.29,1540.23 ; R183.2@5037.62,1315.92 5043.6,1321.91 v1(5043.6,1351.96) ; v1(6025.31,219.06) 6026.93,219.06 6032.37,224.49 6051.47,224.49 6057.28,230.31 C119.2@6057.28,231.22 ; v1(7137.93,768.73) C128.2@7176.68,768.73 7175.09,767.14 U49.6@7175.09,703.87 ; R223.2@7265.02,492.62 v1(7265.02,516.76) ; R224.2@7275.03,677.81 v1(7275.03,706.65)
  Top Layer w15: U13.1@1408.27,1119.73 C32.2@1489.25,1119.73 v1@1489.25,1088.56 ; U11.8@1408.5,1043.59 C33.2@1490.39,1043.59 v1(1490.37,1012.4) ; U27.5@3373.61,1338.74 3423.61,1338.74 3423.82,1338.95 3423.82,1362.88 v1(3424.04,1363.09) ; U31.1@3751.12,1763.03 3751.12,1808.57 v1(3756.5,1813.95)
  SIG 1 w10: v1(5159.85,633.29) 5160.33,633.29 5203.87,676.83 v1(5203.87,1039.77)
  SIG 1 w12: v1(952.36,1998.29) 980.29,1970.36 v1(980.29,1891.03) ; 3708,580 3720.05,580 v1(3734.96,565.09)
  SIG 1 w15: v1(2643.73,500.17) 2659.49,515.93 2766.79,515.93 v1(2807.92,474.79) ; v1(3307.64,1364.45) 3308.45,1364.45 3314.25,1358.64 3418.78,1358.64 3423.23,1363.09 v1(3424.04,1363.09) ; v1(4210.32,1032.7) 4231.97,1054.35
  PWR w10: v1(3496.45,347.6) 3496.91,347.6 3506.3,357 3594.98,357 v1(3693.85,258.12)
  PWR w12: 3408.92,1499.03 3424.04,1483.92 v1(3424.04,1363.09) ; 3570.99,1554.14 3589.47,1554.14 3673.86,1469.75 3673.86,1437.8 v1(3674.02,1437.64) ; 4255.56,1737.76 4255.56,1709.64 4287.76,1677.44 4305.32,1659.88 v1(4305.32,1627.88)
  PWR w15: v1(3958.07,1581.14) 3960.64,1583.71 3962.95,1583.71 3985,1605.77 3985,1707.92 3979.65,1713.27
  Bottom Layer w7: U64.5@551.18,2030.2 592.34,2030.2 C266.2@597.02,2034.88 v1(597.02,2064.5) ; 2264.88,951.34 U61.2@2264.88,973.66 ; v1@2643.82,500.25 U59.3@2643.82,528.96
  Bottom Layer w8: 2264.88,951.34 2285.5,930.72 2296.87,930.72 C257.2@2304.62,922.97 2308.05,926.4 v1(2329.67,926.4)
  Bottom Layer w10: R376.1@1490.39,973.08 v1(1490.37,1012.4) ; R367.1@2005.84,905.59 2008.86,908.61 v1(2034.72,908.61) ; v1(2274.42,770.71) 2275.13,770 R364.1@2345.42,770 ; v1(2459.58,402.06) 2461.75,402.06 2465,405.31 2506.12,405.31 R360.1@2506.66,405.85 ; v1(2490.18,582.06) 2492.34,582.06 2494.36,584.08 R357.1@2529.2,584.08 ; v1(2643.73,500.17) v1@2643.82,500.25 ; v1@3254.61,606.99 3254.61,548.39 3295.23,507.77 R343.2@3309.22,507.77 ; J11.10@3654.17,1900 3666.13,1900 3682.69,1883.44 C239.1@3718.88,1883.44 ; R334.2@3668.3,714.83 3707.44,714.83 R333.1@3711.65,710.62 3760.09,710.62 v1(3776.03,726.55) 3810.46,760.98 3869.23,760.98 3869.55,760.66 3906.56,760.66 R322.2@3907.69,759.53 ; v1(3693.85,258.12) 3693.85,257.93 3703.71,248.08 C237.1@3738.24,248.08 3738.39,247.93 U56.16@3738.39,211 ; v1(4183.68,1138.06) 4183.68,1138.87 4193.23,1148.42 C215.1@4209.06,1148.42 ; v1(4210.32,1032.7) 4215.33,1037.71 C213.1@4215.33,1054.3 ; C211.1@4251.28,1189.39 4260.4,1198.5 v1(4266.66,1198.5) ; C207.1@4270.68,909.64 4266.82,909.64 4256.84,899.66 v1(4254.68,899.66) 4254.68,899.04 4245.44,889.81 4245.44,822.14 4268.19,799.39 C206.2@4280.06,799.39 ; C200.1@4340.5,1173.86 4354.84,1188.2 v1(4356.44,1188.2) ; C186.1@4431.7,915.21 4431.51,915.03 4431.51,896.64 v1(4430.08,895.21) 4431.61,893.68 4431.61,890.89 4437.14,885.35 4437.14,821.9 C180.2@4434.01,818.76 ; v1(4481.93,1031.41) 4484.09,1031.41 C172.1@4494.96,1042.28 ; v1(4496.21,1090.65) 4498.47,1092.91 C174.1@4498.47,1106.41 ; v1(4692.03,1691.44) 4698.3,1685.18 C163.2@4729.47,1685.18 ; R301.1@5088.74,1538.08 5090.22,1539.57 v1(5119.23,1539.57) ; v1(5159.85,633.29) 5158.88,634.26 5158.88,651.59 5170.35,663.06 5190.88,663.06 C154.1@5191.31,663.49 5231.54,663.49 5246.6,678.55 U54.1@5263.12,678.55 ; v1(5203.87,1039.77) 5250.13,993.51 U54.17@5263.12,993.51 ; U54.30@5393.04,836.03 v1(5439,836) ; v1(5548.23,1244.66) 5649.6,1244.66 5649.68,1244.58 R275.1@5676.49,1244.58 ; R266.1@5892.01,1248.51 5957.23,1248.51 v1(5957.45,1248.29) ; R258.1@5933.83,1609.41 5935.3,1609.41 5942.11,1616.22 5942.11,1630.93 5948.78,1637.6 v1(5948.78,1639.76) ; R259.1@5933.83,1674.05 v1(5933.83,1703.75) ; R260.1@5933.83,1736.2 v1(5933.83,1768.87) ; R257.2@5994.28,395.65 5994.69,396.06 6017.13,396.06 v1(6017.55,396.47) ; U50.5@6182.93,1294.77 6182.93,1357.12 C143.1@6184.13,1358.32 6226.91,1358.32 6243.03,1374.44 v1(6244.74,1374.44) ; R240.2@6490.52,94.86 6490.52,59.16 6516.11,33.56 6688.13,33.56 6708.54,53.97 R234.2@6708.54,90.62 ; v1(6534.11,1879.65) 6536.05,1877.71 R238.1@6585.42,1877.71 ; v1(6782.48,1949.68) R232.2@6804.23,1949.67 ; R230.2@6830.2,1400.32 R227.2@6830.2,1349.46 v1(6858.43,1349.46) ; R228.2@6830.2,1448.74 R229.2@6830.2,1497.54 6858.43,1497.54 v1(6858.47,1497.59) ; v1(7091.5,472.45) 7091.56,472.38 R226.2@7091.56,442.03 ; v1(7091.56,332.08) R225.2@7091.56,363.62
  Bottom Layer w12: v1(377.93,2074.5) R410.2@410.78,2074.5 ; v1(952.36,1998.29) R395.2@952.36,2032.93 ; U62.5@979.41,1860.75 979.41,1890.15 v1(980.29,1891.03) ; R389.2@1079.41,1916.21 1105.13,1916.21 1110.35,1910.99 v1(1111.97,1910.99) ; R378.2@1335.24,2047.88 1337.98,2050.63 v1(1377.8,2050.63) ; R377.1@1489.25,1177.74 1489.25,1197.97 v1(1509.54,1218.26) ; v1@1490.39,870.17 R375.1@1490.39,904.65 ; v1@1949.86,1046.48 1949.86,996.83 v1@1950.37,996.31 ; v1(1950.36,1097.68) 1949.43,1097.68 1948.83,1097.08 1948.83,1049.3 v1(1951.13,1046.99) ; v1(1951.13,936.88) v1(1951.13,996.31) ; v1(2353.24,1197.58) 2354.09,1196.73 2354.09,1184.25 2363.4,1174.94 2383.89,1174.94 C256.2@2386.73,1172.1 ; U60.5@2386.73,1229.7 C256.2@2386.73,1172.1 ; C256.2@2388.15,1170.68 C256.2@2386.73,1172.1 ; v1(2499.01,1217.89) 2499.12,1218 R361.2@2499.12,1253.66 ; U57.16@3735.52,504.21 3735.52,542.42 C238.2@3735.85,542.75 3734.3,544.29 3734.3,564.44 v1(3734.96,565.09) 3739.56,569.7 3813.93,569.7 3882.63,501 3900.96,501 3901.03,500.93 3919.98,500.93 3920.05,501 3931.21,501 3969.28,539.08 4023.23,539.08 4030.26,532.05 4030.26,515.13 4036.07,509.32 C233.2@4036.55,509.32 4038.17,510.95 4062.01,510.95 v1(4063.16,512.1) ; v1(3779.5,945.02) 3809.45,974.97 3844.33,974.97 3864.23,994.87 3919.41,994.87 3921.24,993.04 C234.2@3988.32,993.04 4007.75,993.04 4025.95,1011.24 FB4.1@4046.21,1011.24 ; v1(3958.07,1581.14) 3959.69,1581.14 3965.81,1575.01 C231.2@4017.75,1575.01 ; R316.1@4304.66,1604.76 4304.66,1627.23 v1(4305.32,1627.88) 4305.32,1650.36 C198.2@4304.66,1651.01 ; v1(4480.47,1223.93) 4480.47,1216.85 C177.1@4482.22,1215.11 ; v1(4800.44,1568.29) 4800.24,1568.09 C160.2@4800.24,1540.83 4836.53,1540.83 4846.94,1530.43 U55.5@4892.58,1530.43 ; C156.1@5162.89,1040.23 5203.41,1040.23 v1(5203.87,1039.77) ; v1(6025.31,219.06) 6025.58,219.33 U52.5@6057.99,219.33 ; v1(6534.11,1852.25) 6557.59,1828.78 R237.2@6582.96,1828.78
  Bottom Layer w15: R356.1@2770.91,474.92 2771.03,474.79 v1(2807.92,474.79) 2834.87,501.74 2834.87,576.81 2811.78,599.89 2771.07,599.89 R355.1@2770.98,599.99 2770.98,690.51 2786.24,705.77 R353.1@2821.99,705.77 2824.33,708.11 2824.33,726.57 2844.82,747.07 v1(2883.18,747.07) 2950.82,747.07 2960.23,737.65 v1(2960.23,646.74) ; R344.2@3307.64,1338.26 v1(3307.64,1364.45)
  other v1: 3498,398 3477.56,398.54 3186.34,609.1 3217.85,609.1 3254.61,609.1 3201.81,635.38 3235.08,635.38 3187.64,663.03 3217.85,663.03 3248.91,663.03 1490.37,870.15 4726.28,1025.38 1489.23,1088.54
VSYS_3V3_BP: J1/J3.1 J5/J7.41 J13.2 | length 2835.6
  PWR w20: J1/J3.1@1454.17,100 1530.24,23.93 2360.71,23.93 2436.78,100 2601.43,100 2651.43,150 3077.48,150 3168.33,59.15 3168.33,-60.77 3201.79,-94.23 3759.94,-94.23 J5/J7.41@3954.17,100
VSYS_5V0: C39.1 C41.1 C44.1 C45.2 C60.1 C61.1 C62.1 C63.1 C80.1 C142.2 C144.1 C145.1 C147.1 C242.1 C251.1 C252.1 C254.1 J18.4 J19.4 R44.2 R79.2 R83.2 R84.2 R192.2 R280.2 R281.2 R296.2 R297.2 R298.2 R299.2 R300.2 R318.2 R346.2 U14.7 U14.8 U20.6 U28.9 U28.14 U28.18 U52.3 U53.19 | length 7913
  Top Layer w10: U14.7@1654.12,403.52 1675.88,403.52 1683.64,411.29 ; U14.8@1654.12,423.21 1674.07,423.21 1683.64,432.77 ; R79.2@2647.24,1117.64 2647.24,1137.24 v1(2651.55,1141.56) ; v1(2740.79,1242.07) 2742.32,1240.54 2760.72,1240.54 R83.2@2763.68,1237.58 ; R84.2@2851.59,1052.36 v1(2851.59,1079.89) ; 3260.24,401.23 U28.9@3290.99,401.23 ; 3299,277 3302.4,277 3316.58,291.18 U28.14@3316.58,316.58 ; U28.18@3395.32,316.58 3395.32,297.68 3414.58,278.42
  Top Layer w12: v1(3486.39,253.5) 3487.06,254.17 3487.06,272.5 C80.1@3487.74,273.17 ; R192.2@5394.32,1501.35 5395.03,1501.35 5400.84,1507.16 5400.84,1523.84 v1(5416,1539)
  Top Layer w15: C63.1@3221.59,396.5 3221.59,400.43 3225.91,404.75 3240.56,404.75 3240.6,404.79 3258.59,404.79 3260.09,403.3
  Top Layer w20: v1(5635.37,1553.4) 5676.52,1594.54 J18.4@5676.52,1714.55 5676.52,1758.72 v1(5635.69,1799.55) 5635.69,1923.72 J19.4@5676.52,1964.55 ; v1(5965.47,-17.99) 5965.47,48.47 6063.12,146.12 6159.12,146.12 v1(6255,242)
  SIG 1 w10: v1(2740.79,1242.07) 2724.45,1242.07 2651.55,1169.17 v1(2651.55,1141.56) 2713.22,1079.89 v1(2851.59,1079.89)
  SIG 1 w12: 4074,549 4074.92,549.92 4110.52,549.92 4118.68,541.76 v1(4120.3,541.76)
  SIG 1 w20: v1(4941.07,95.54) 4968.45,95.54 5106.99,-43 5940.45,-43 v1(5965.47,-17.99) ; v1(5092.59,1874.13) 5106.69,1888.23 5156.21,1888.23 5202.8,1841.64 5202.8,1830.99 5234.24,1799.55 5318.14,1799.55 5344.62,1826.03 5485.03,1826.03 v1(5511.52,1799.55) 5513.14,1799.55 5537.02,1823.42 5611.82,1823.42 v1(5635.69,1799.55) ; v1(5331.52,1548.78) 5332.02,1548.78 5341.81,1539 v1(5416,1539) ; v1@5416.2,1539 5441.47,1513.73 5478.45,1513.73 v1(5506.27,1541.55) 5537.76,1573.03 5615.73,1573.03 v1(5635.37,1553.4) ; v1(5547.45,1397.82) 5577.5,1367.76 5935.76,1367.76 5975.21,1407.21 5975.21,1437.53 5994.27,1456.6 6521.1,1456.6 6817,1160.69 6817,506 6653,342 6421,342 6312.25,233.25 6263.75,233.25 v1(6255,242)
  PWR w20: v1(5506.27,1541.55) 5536.63,1511.18 5536.63,1408.63 v1(5547.45,1397.82)
  Bottom Layer w10: v1(5092.59,1874.13) 5093.07,1874.13 5107.66,1888.72 R300.2@5107.66,1892.65 ; U53.19@5514.38,1306.36 5514.38,1347.35 5525.89,1358.85 C147.1@5544.69,1358.85 ; v1(5547.45,1397.82) 5547.45,1367.51 C147.1@5550.4,1364.56
  Bottom Layer w12: v1(2412.04,843.84) 2413.18,842.69 2423.8,842.69 2468.02,798.47 2530.28,798.47 2576.94,845.13 2628.4,845.13 2651.55,868.28 v1(2651.55,1141.56) ; R298.2@5316.52,1583.8 5321.02,1579.3 5321.02,1559.29 v1(5331.52,1548.78) ; v1(5316.52,1799.55) R299.2@5316.52,1833.8 ; v1@5511.52,1548.42 R296.2@5511.52,1583.8 ; v1(5511.52,1799.55) R297.2@5511.52,1833.8 ; v1(5635.37,1553.4) 5635.53,1553.56 5635.53,1583.64 R280.2@5635.69,1583.8 ; v1(5635.69,1799.55) R281.2@5635.69,1833.8 ; U52.3@6168.23,244.92 6191.46,244.92 6198.35,238.03 6249.4,238.03 6253.38,242 v1(6255,242)
  Bottom Layer w15: J18.4@5676.52,1714.55 5695.69,1695.37 C144.1@5695.69,1631.04 ; J19.4@5676.52,1964.55 5695.69,1945.37 C145.1@5695.69,1881.04
  other v1: 3271.47,288.3 3246.48,295.51 3226.9,308.72 1762.88,374.08 1800.59,374.08 1838.63,374.08 1876.49,374.08 1914.55,374.08 1949.19,374.08 1779.99,398.69 1818.66,398.69 1857.07,398.69 1893.55,398.69 1933.18,398.69 3070.9,410.2 3096.27,425.02 1913.96,427.52 3070.02,441 3096.05,459.14 3068.61,472.57
VSYS_5V0_BP_1: J1/J3.21 J27.2
VSYS_5V0_BP_2: J5/J7.61 J26.2
VSYS_MON_AM261: C224.1 R318.1 R319.2 U34.Y4 | length 239.4
  Top Layer w5.3: U34.Y4@4171.26,811.38 4172.4,810.24 4172.4,782.71 4178.15,776.96 v1(4178.15,773.52)
  Bottom Layer w7: C224.1@4172.05,686.43 4172.05,764.44 4178.15,770.55 v1(4178.15,773.52) ; R318.1@4172.34,577.42 R319.2@4172.34,647.28 C224.1@4172.34,686.43
VSYS_TA_3V3: C11.1 C20.1 C36.1 C37.2 C42.2 C43.2 C258.2 R39.1 R43.1 R366.1 R367.2 R368.1 R369.1 R370.1 R371.1 R372.1 R373.1 R401.1 R403.2 R409.2 U5.8 U7.8 U9.16 U15.5 U16.14 U16.15 U18.5 U61.3 | length 1355
  Top Layer w10: U16.14@1799.29,984.42 1799.29,965.03 1807.83,956.48 ; 1809.5,954.81 1807.83,956.48 ; U16.15@1818.97,984.42 1818.97,967.62 1807.83,956.48
  Top Layer w12: v1(489.98,1959.79) 490.32,1959.45 490.32,1937.23 C11.1@490.66,1936.89 490.66,1848.27 U5.8@491.82,1847.11 ; v1(711.42,1905.81) C20.1@711.42,1871.77 729.35,1871.77 751.8,1849.31 U7.8@777.09,1849.31 ; U9.16@1484.79,1687.95 C36.1@1581.16,1687.95 1581.16,1703.97 1574.13,1711 v1(1551,1711) ; v1(1706.73,1505.08) 1706.73,1470.61 C37.2@1708.1,1469.23 1707.36,1468.49 U15.5@1707.36,1416.81 ; R43.1@1869.25,882.86 v1(1888.79,882.86) ; v1(1944.75,1535.77) C43.2@1944.75,1505.08 1946.1,1503.73 U18.5@1946.1,1437.28
  Top Layer w15: C42.2@1809.5,930.1 1809.5,954.81
  Top Layer w20: v1(1607.16,1029.69) R39.1@1643.53,1029.69 ; v1(1777.33,930.1) C42.2@1809.5,930.1 C42.2@1810.11,929.49
  Bottom Layer w7: 2244.62,948.57 2249.13,953.08 U61.3@2249.13,973.66
  Bottom Layer w12: v1(461.61,1870.74) R409.2@491.82,1870.74 ; R403.2@641.82,1870.74 v1(673.06,1870.74) ; v1(776.99,1908.23) 777.09,1908.14 R401.1@777.09,1872.94 ; v1(1581.16,1355.28) R368.1@1581.16,1387.95 R369.1@1581.16,1437.95 R370.1@1581.16,1487.95 R371.1@1581.16,1537.95 R372.1@1581.16,1587.95 R373.1@1581.16,1637.95 ; R367.2@2005.84,858.35 2033.09,858.35 v1(2033.9,859.16) ; C258.2@2244.62,922.97 2244.62,948.57
  Bottom Layer w20: R366.1@2130.45,927.14 2134.39,927.14 2136.2,925.33 2136.2,905.27 2147.91,893.55 2204.04,893.55 2215.76,905.27 v1(2215.76,917.37) 2219.81,921.42 C258.2@2244.62,921.42
VSYSA_1V8: FB1.2 S2.1 S2.4 | length 217.2
  Top Layer w18: S2.4@5530.99,268.94 S2.1@5676.66,268.94 FB1.2@5748.15,268.94
VUSB_5V0: C12.1 C15.1 C22.1 C27.1 C31.1 C35.1 C47.1 C49.2 J26.1 J27.1 L1.2 R14.2 R16.2 R20.1 R21.1 R411.1 TP1.1 U6.12 U8.5 U10.5 U14.1 U14.2 U14.4 U22.5 | length 825.4
  Top Layer w7: U6.12@658.3,257.8 659.55,256.55 661.5,256.55 661.94,256.12 U6.12@661.94,250.21
  Top Layer w8: U6.12@658.3,257.8 658.3,259.7
  Top Layer w10: 1549.79,411.29 1557.56,403.52 U14.2@1579.32,403.52 ; 1549.79,432.77 1559.36,423.21 U14.1@1579.32,423.21 ; v1(1575.69,342.77) 1577.22,344.3 1577.22,364.07 1577.29,364.15 U14.4@1579.32,364.15
  Top Layer w12: v1(536.3,247.37) 536.3,413.31 v1(539.2,416.22) ; v1(636.73,333.56) 637.65,332.64 C15.1@637.65,301.51 639.27,299.89 639.27,278.73 658.3,259.7 ; R16.2@796.49,139.29 798.91,141.7 v1(798.91,167.7) ; R21.1@855.23,302.53 855.31,302.61 R21.1@855.31,303.91 855.31,329.24 862.34,336.27 v1(880.29,336.27) C22.1@921.05,336.27 C22.1@920.9,336.11 ; U8.5@920.9,268.35 C22.1@920.9,336.27
  Top Layer w15: v1(679.97,48.23) R14.2@679.97,84.62 ; R20.1@855.31,146.28 855.36,146.33 885.12,146.33 v1(885.16,146.38) ; v1(1016.88,413.97) 1017.44,413.41 C27.1@1017.44,377.24 1077.75,377.24 U10.5@1085.63,385.12
  Bottom Layer w12: R411.1@446.4,439.51 515.91,439.51 v1(539.2,416.22)
  other v1: 450.31,190.05 478.98,190.05 507.64,190.05 536.3,190.05 564.96,190.05 450.31,218.71 478.98,218.71 507.64,218.71 536.3,218.71 564.96,218.71 1243.83,321.32 1278.83,321.32 1313.83,321.32 1348.83,321.32 2221.19,338.39 1243.83,371.32 1278.83,371.32 1313.83,371.32 1348.83,371.32 2222.08,387.7 1243.83,421.32 1278.83,421.32 1313.83,421.32 1348.83,421.32
XDS_DEBUG_ID4: R24.1 R394.1 U63.63 | length 243.6
  Top Layer w5.3: R24.1@1007.5,1552.81 1007.64,1552.95 v1(1029.86,1552.95)
  Bottom Layer w5.3: U63.63@873.85,1477.52 873.85,1510.53 881.22,1517.9 997.5,1517.9 1007.5,1527.9 1007.5,1552.81 1007.64,1552.95 v1(1029.86,1552.95)
XDS_DEBUG_ID5: R23.1 R396.1 U63.62 | length 232.5
  Top Layer w5.3: R23.1@945.89,1519.68 964.23,1519.68 971.1,1526.55 v1(971.1,1555)
  Bottom Layer w5.3: U63.62@858.1,1477.52 858.1,1512.91 874.54,1529.36 935.1,1529.36 943.35,1537.6 R396.1@943.35,1555 v1(971.1,1555)
XDS_DEBUG_ID6: R22.1 R398.1 U63.61 | length 203.6
  Top Layer w5.3: R22.1@866.99,1519.68 900.47,1519.68 915,1534.21 v1(915,1555)
  Bottom Layer w5.3: U63.61@842.35,1477.52 842.35,1518.57 878.78,1555 R398.1@889.13,1555 v1(915,1555)
XDS_DEBUG_ID7: R19.1 R399.1 U63.60 | length 140.6
  Top Layer w5.3: R19.1@815,1519.68 815.45,1520.13 815.45,1545.32 v1(815.77,1545.65)
  Bottom Layer w5.3: v1(815.77,1545.65) 825.13,1555 R399.1@842.24,1555 842.24,1533.73 826.6,1518.09 U63.60@826.6,1477.52
XDS_EMU0: R9.1 U63.42 | length 67.4
  Top Layer w5.3: v1(539.2,1519.68) 539.37,1519.85 R9.1@539.37,1543.19
  Bottom Layer w5.3: v1(539.2,1519.68) 543.14,1515.75 U63.42@543.14,1477.52
XDS_EMU1: R12.1 U63.43 | length 82.4
  Top Layer w5.3: v1(563.03,1429.89) 569.47,1423.45 R12.1@569.47,1399.46
  Bottom Layer w5.3: U63.43@558.89,1477.52 558.89,1434.03 v1(563.03,1429.89)
XDS_PROGSTAZ1: R1.2 U63.4 | length 768
  Top Layer w5.3: R1.2@100.66,1565.68 v1(130.97,1565.68)
  SIG 1 w4.75: v1(130.97,1565.68) 324.66,1371.99 324.66,1039.04 v1(386.18,977.52)
  Bottom Layer w5.3: U63.4@342.35,977.52 v1(386.18,977.52)
XDS_PROGSTAZ2: R2.2 U63.3 | length 916.4
  Top Layer w5.3: R2.2@102.71,1626.75 v1(133.02,1626.75)
  SIG 1 w4.75: v1(133.02,1626.75) 133.02,1610.36 345.55,1397.83 345.55,1054.8 422.84,977.52 v1(436.18,977.52)
  Bottom Layer w5.3: U63.3@342.35,961.77 374.31,961.77 378.09,958 416.65,958 v1(436.18,977.52)
XDS_VBUS_DETECT: C269.2 R414.2 R415.1 U63.1 | length 288.7
  Bottom Layer w5.3: R415.1@172.52,999.2 174.49,999.2 204.56,1029.27 204.56,1049.43 C269.2@205,1049.87 ; C269.2@205.06,1049.8 R414.2@251.47,1049.8 251.47,1022.76 302.51,971.71 302.51,936.14 308.38,930.28 U63.1@342.35,930.28
XDSET_1_D_N: J24.2 U1.1 U1.10 U63.93 | length 1271.8
  Top Layer w4.2: J24.2@11.81,1046.6 43.09,1046.6 51.29,1054.79 76.14,1054.79 81.38,1049.55 U1.10@88.56,1049.55 94.8,1049.55 100.05,1054.79 109.01,1054.79 114.25,1049.55 U1.1@121.44,1049.55 128.62,1049.55 133.86,1054.79 146.6,1054.79 v1(160,1041.39)
  SIG 1 w4: v1(160,1041.39) 171.72,1053.11 188.1,1053.11 199.9,1041.31 199.9,935.86 224.28,911.48 377.81,911.48 400.51,888.78 767.1,888.78 795,916.68 795,958.94 776.42,977.52 750.13,977.52 v1(740,987.65)
  Bottom Layer w4.2: v1(740,987.65) 753.4,974.25 917.83,974.25 921.1,977.52 U63.93@948.65,977.52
